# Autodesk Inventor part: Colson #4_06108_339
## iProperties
Shininess: 64.0
Length Units: 11272
Angle Units: 11279
Time Units: 11290
Mass Units: 11286
Length Display Precision: 3
Angle Display Precision: 2
Compacted: True
Part Number: Colson #4_06108_339
Document SubType Name: Modeling
Created: 2003-06
Designer: ARennick
Manufacturer: Standard
Standards Organization: Custom
Description: Series 4 (1250lb) Swivel Caster, Standard Mount Plate, 6 dia, Phenolic wheel.
Catalog Web Link: www.colsoncaster.com
Density: 0.0
Volumn: 0.0
Area: 0.0
PropertySet Name: Model Information
Control State: 0
Master: False
Checked Out: False
Author: ARennick
Comments: These are basically 5 sizes of caster with different part numbers used for the materials. Thanks as always to Charles for the dissemination of these things.
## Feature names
1. Top Plate [Extrusion]
2. Flange [Extrusion]
3. Nut [Extrusion]
4. Flange Mir [Mirror]
5. Mirror4
6. Bolt Shaft [Extrusion]
7. Revolution3
8. Fillet3
